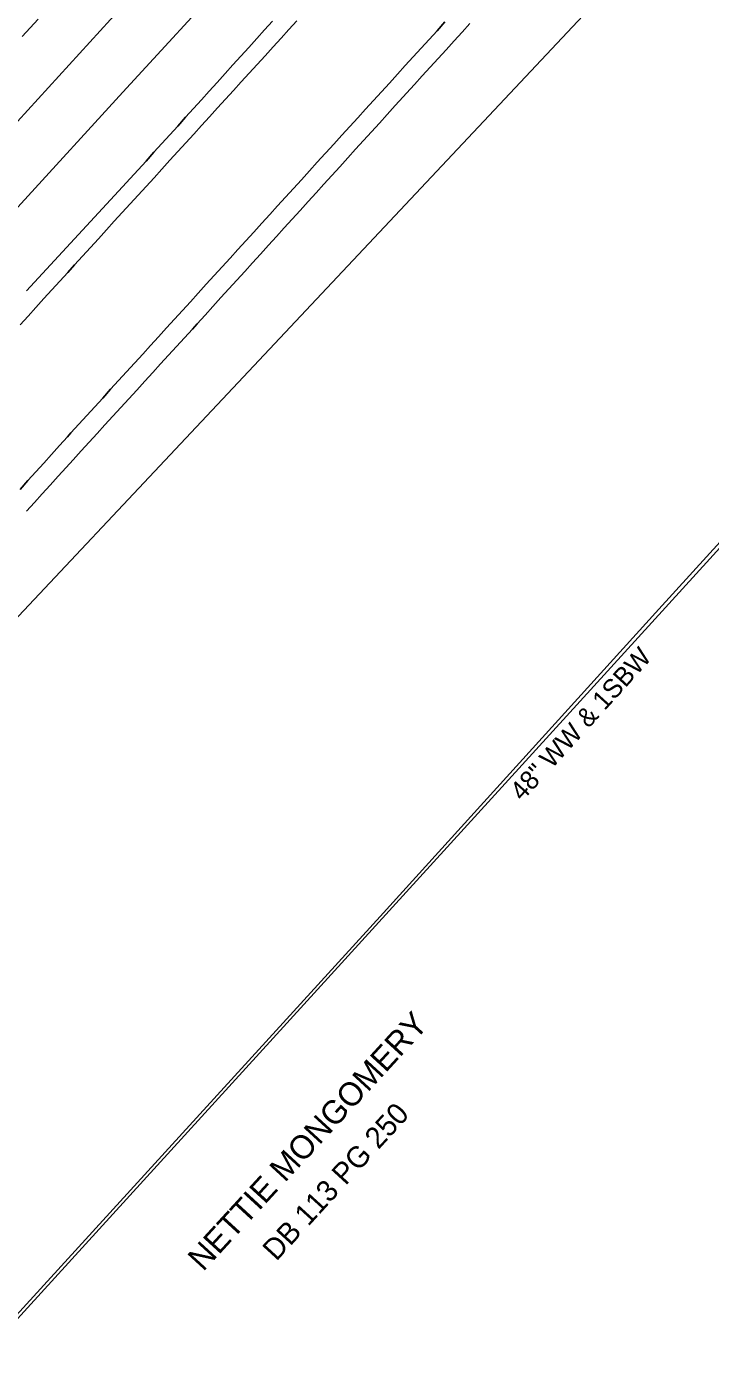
# Model space of a CAD drawing. Extents: x 1806071 to 1809844, y 912722 to 917035.
# Drawn here: x 1808850.7 to 1808995.8, y 915508.9 to 915790.1 of the extents above; entities that cross this region are included whole.
import ezdxf

# ---------------------------------------------------------------- set-up
doc = ezdxf.new("R2010")
doc.units = 0
for name, color, linetype in [('Exist Guardrail Cable Guide Rail', 7, 'Continuous'), ('Exist Horizontal Alignment', 7, 'Continuous'), ('Exist Other Culture Fence Line', 7, 'Continuous'), ('Exist Other Culture Fence Line Text', 7, 'Continuous'), ('Exist Property Deed Book Text', 7, 'Continuous'), ('Exist Property Owner Text', 7, 'Continuous'), ('Exist Right of Way Line', 7, 'Continuous'), ('Exist Roads EOP', 7, 'Continuous'), ('Exist Roads EOT', 7, 'Continuous'), ('Exist Vegetation Woods Line', 7, 'Continuous')]:
    doc.layers.add(name, color=color, linetype=linetype)

msp = doc.modelspace()

# ---------------------------------------------------------------- linework, layer by layer
at = {"layer": 'Exist Guardrail Cable Guide Rail'}
msp.add_lwpolyline([(1808684.67, 915571.48), (1808707.85, 915596.81), (1808731.14, 915622.16), (1808755.12, 915648.61), (1808779.28, 915675.16), (1808802.71, 915700.82), (1808824.91, 915725.61), (1808849.56, 915752.56), (1808871.11, 915776.15), (1808894.68, 915801.79), (1808917.65, 915827.17), (1808930.41, 915842.51)], dxfattribs=at)
at = {"layer": 'Exist Horizontal Alignment'}
msp.add_line((1806073.69, 912724.84), (1809374.2, 916346.52), dxfattribs=at)
at = {"layer": 'Exist Other Culture Fence Line'}
msp.add_lwpolyline([(1809083.03, 915774.32), (1808984.81, 915666.52), (1808925.72, 915601.39), (1808852.14, 915520.8), (1808595.36, 915239.5)], dxfattribs=at)
at = {"layer": 'Exist Right of Way Line'}
msp.add_line((1809840.95, 916604.82), (1808525.76, 915161.65), dxfattribs=at)
at = {"layer": 'Exist Roads EOP'}
for points in [[(1808849.74, 915787.95), (1808851.43, 915789.79), (1808853.12, 915791.64)], [(1808902.86, 915791.22), (1808901.18, 915789.36), (1808899.5, 915787.51), (1808897.83, 915785.65), (1808896.15, 915783.8), (1808894.47, 915781.94), (1808892.8, 915780.09), (1808891.12, 915778.23), (1808889.44, 915776.38), (1808887.77, 915774.53), (1808886.09, 915772.67), (1808884.42, 915770.82), (1808882.74, 915768.96), (1808881.06, 915767.11), (1808879.39, 915765.25), (1808877.71, 915763.4), (1808876.03, 915761.54), (1808874.36, 915759.69), (1808872.68, 915757.83), (1808871.07, 915756.05), (1808869.37, 915754.22), (1808867.67, 915752.38), (1808865.97, 915750.55), (1808864.27, 915748.72), (1808862.57, 915746.88), (1808860.87, 915745.05), (1808859.17, 915743.22), (1808857.47, 915741.38), (1808855.77, 915739.55), (1808854.07, 915737.71), (1808852.37, 915735.88), (1808850.68, 915734.05)], [(1808850.69, 915687.32), (1808852.35, 915689.15), (1808854.03, 915691.01), (1808855.7, 915692.86), (1808857.38, 915694.71), (1808859.06, 915696.56), (1808860.58, 915698.23), (1808862.26, 915700.08), (1808863.95, 915701.93), (1808865.64, 915703.77), (1808867.32, 915705.62), (1808869.01, 915707.46), (1808870.69, 915709.31), (1808872.38, 915711.16), (1808874.07, 915713), (1808875.75, 915714.85), (1808877.44, 915716.69), (1808879.12, 915718.54), (1808880.81, 915720.39), (1808882.5, 915722.23), (1808884.18, 915724.08), (1808885.87, 915725.92), (1808886.87, 915727.02), (1808888.55, 915728.87), (1808890.23, 915730.73), (1808891.91, 915732.58), (1808893.59, 915734.43), (1808895.27, 915736.28), (1808896.95, 915738.13), (1808898.63, 915739.98), (1808900.32, 915741.83), (1808902, 915743.68), (1808903.68, 915745.53), (1808905.36, 915747.39), (1808907.04, 915749.24), (1808908.72, 915751.09), (1808910.4, 915752.94), (1808912.08, 915754.79), (1808913.76, 915756.64), (1808915.44, 915758.49), (1808917.12, 915760.34), (1808918.8, 915762.2), (1808920.48, 915764.05), (1808922.16, 915765.9), (1808923.84, 915767.75), (1808925.52, 915769.6), (1808927.2, 915771.45), (1808928.88, 915773.3), (1808930.56, 915775.15), (1808931.25, 915775.92), (1808932.94, 915777.77), (1808934.62, 915779.62), (1808936.31, 915781.46), (1808937.99, 915783.31), (1808939.68, 915785.16), (1808941.36, 915787), (1808943.05, 915788.85), (1808944.73, 915790.7)]]:
    msp.add_lwpolyline(points, dxfattribs=at)
at = {"layer": 'Exist Roads EOT'}
for points in [[(1808849.3, 915691.93), (1808850.97, 915693.79), (1808852.65, 915695.65), (1808854.32, 915697.5), (1808856, 915699.36), (1808857.67, 915701.21), (1808859.35, 915703.07), (1808860.1, 915703.91), (1808861.79, 915705.76), (1808863.47, 915707.6), (1808865.16, 915709.45), (1808866.84, 915711.3), (1808868.52, 915713.15), (1808870.21, 915714.99), (1808871.89, 915716.84), (1808873.58, 915718.69), (1808873.65, 915718.77), (1808875.33, 915720.62), (1808877.01, 915722.46), (1808878.7, 915724.31), (1808880.38, 915726.16), (1808882.06, 915728.01), (1808883.75, 915729.86), (1808885.43, 915731.71), (1808887.11, 915733.56), (1808888.79, 915735.41), (1808890.48, 915737.25), (1808892.16, 915739.1), (1808893.84, 915740.95), (1808895.53, 915742.8), (1808897.21, 915744.65), (1808898.89, 915746.5), (1808900.57, 915748.35), (1808902.26, 915750.2), (1808903.94, 915752.04), (1808905.62, 915753.89), (1808907.31, 915755.74), (1808908.99, 915757.59), (1808910.67, 915759.44), (1808912.35, 915761.29), (1808914.04, 915763.14), (1808914.19, 915763.31), (1808915.87, 915765.15), (1808917.56, 915767), (1808919.24, 915768.85), (1808920.92, 915770.7), (1808922.61, 915772.55), (1808924.29, 915774.4), (1808925.97, 915776.25), (1808927.66, 915778.09), (1808929.34, 915779.94), (1808931.02, 915781.79), (1808932.71, 915783.64), (1808934.39, 915785.49), (1808936.07, 915787.34), (1808937.76, 915789.18), (1808939.44, 915791.03)], [(1808908.03, 915791.27), (1808906.35, 915789.42), (1808904.66, 915787.57), (1808902.98, 915785.73), (1808901.3, 915783.88), (1808899.61, 915782.03), (1808897.93, 915780.19), (1808896.24, 915778.34), (1808894.56, 915776.49), (1808892.87, 915774.64), (1808891.19, 915772.8), (1808889.51, 915770.95), (1808887.82, 915769.1), (1808886.14, 915767.25), (1808884.45, 915765.41), (1808882.77, 915763.56), (1808881.08, 915761.71), (1808879.4, 915759.86), (1808877.72, 915758.02), (1808876.03, 915756.17), (1808874.35, 915754.32), (1808872.66, 915752.47), (1808870.98, 915750.63), (1808869.29, 915748.78), (1808867.61, 915746.93), (1808865.92, 915745.08), (1808864.24, 915743.24), (1808862.56, 915741.39), (1808860.87, 915739.54), (1808859.41, 915737.94), (1808857.73, 915736.09), (1808856.05, 915734.24), (1808854.37, 915732.38), (1808852.69, 915730.53), (1808851.01, 915728.68), (1808849.33, 915726.83)]]:
    msp.add_lwpolyline(points, dxfattribs=at)
at = {"layer": 'Exist Vegetation Woods Line'}
msp.add_lwpolyline([(1808397.76, 915010.37), (1808398.17, 915063.08), (1808401.78, 915078.95), (1808456.47, 915136.33), (1808525.87, 915216.84), (1808588.47, 915298.84), (1808603.34, 915378.8), (1808593.62, 915389.17), (1808703.69, 915510.62), (1809133.9, 915968.11), (1809176.35, 915989.33), (1809248.65, 915971.39)], dxfattribs=at)

# ---------------------------------------------------------------- texts
at = {"layer": 'Exist Other Culture Fence Line Text'}
msp.add_text('48" WW & 1SBW', height=4, rotation=47.7823, dxfattribs=at).set_placement((1808955.83, 915625.66))
at = {"layer": 'Exist Property Deed Book Text'}
msp.add_text('DB 113 PG 250', height=4.5, rotation=47.5843, dxfattribs=at).set_placement((1808903.67, 915528.14))
at = {"layer": 'Exist Property Owner Text'}
msp.add_text('NETTIE MONGOMERY', height=5, rotation=47.4554, dxfattribs=at).set_placement((1808888.15, 915525.95))

doc.saveas('drawing.dxf')
